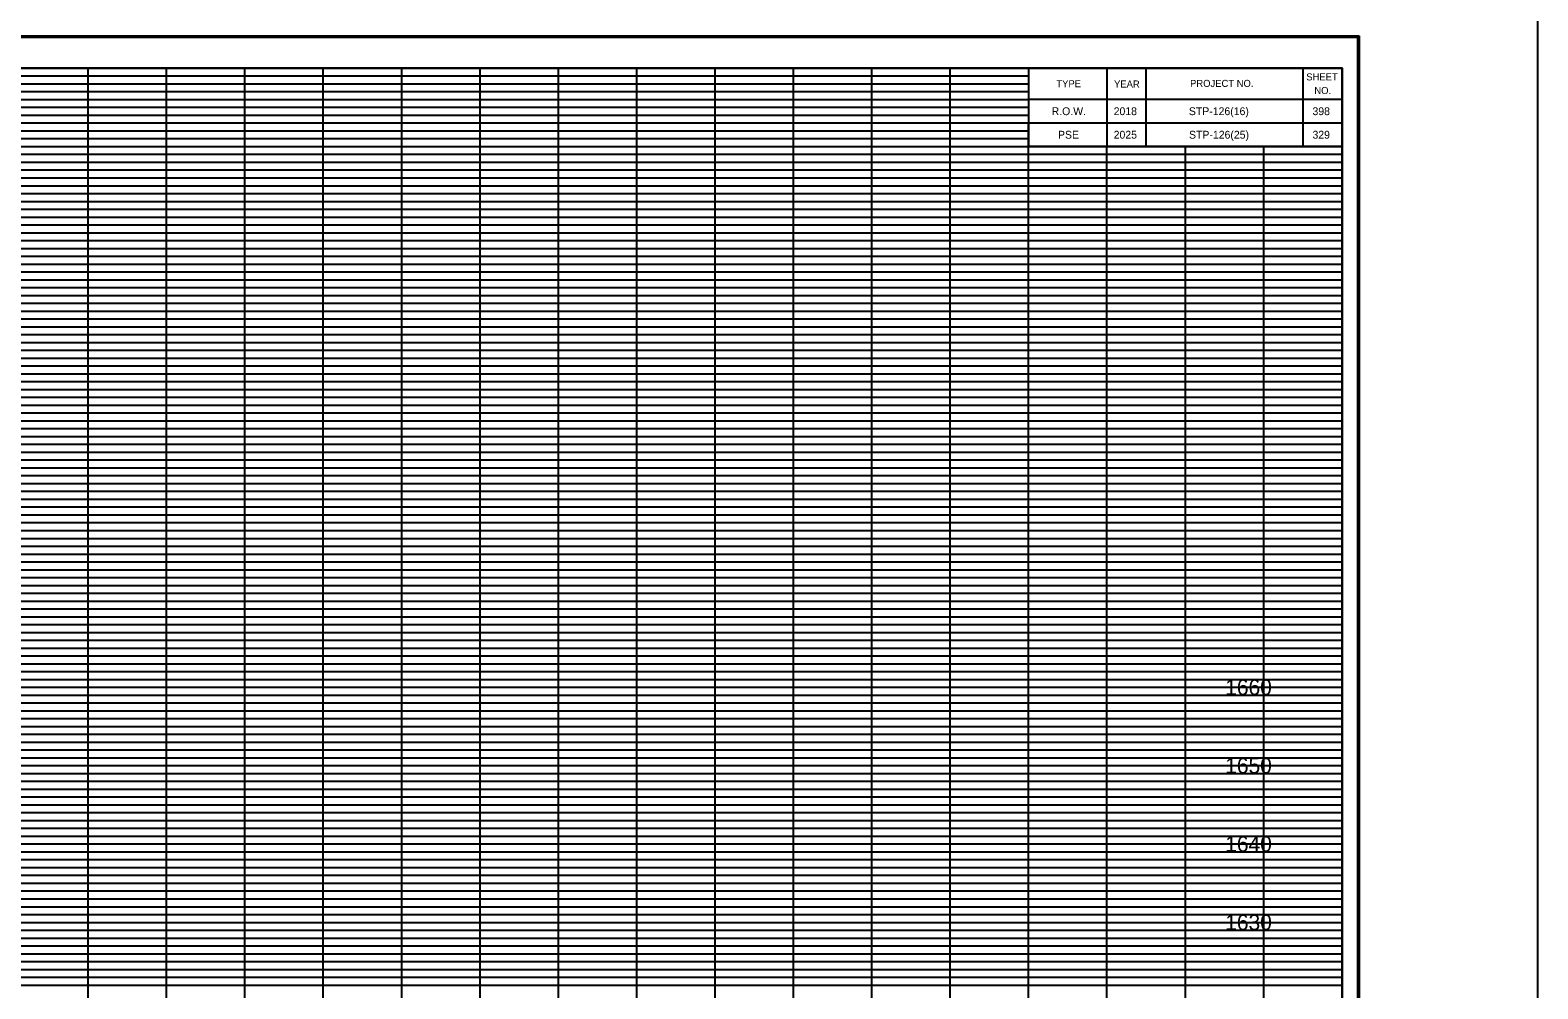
# Model space of a CAD drawing. Extents: x 955 to 1375, y 1248 to 3657.
# Drawn here: x 1152.6 to 1345, y 2982.5 to 3104.8 of the extents above; entities that cross this region are included whole.
import ezdxf

# ---------------------------------------------------------------- set-up
doc = ezdxf.new("R2010")
doc.units = 0
for name, color, linetype in [('DESIGN - SCRATCH - User 1', 7, 'Continuous'), ('DESIGN - SHEET - Corner Text', 7, 'Continuous'), ('DESIGN - SHEET - Light Grid', 7, 'Continuous'), ('DESIGN - SHEET - Linework', 7, 'Continuous'), ('DESIGN - SHEET - Plot Shape', 7, 'Continuous'), ('DESIGN - TYPICAL - Text', 7, 'Continuous'), ('DESIGN - UTILITIES - Cable (Overhead) with Text', 7, 'Continuous'), ('SURVEY - NON-TRANSPORTATION - Features Text', 7, 'Continuous')]:
    doc.layers.add(name, color=color, linetype=linetype)

# ---------------------------------------------------------------- blocks, each defined once
blk = doc.blocks.new('XSTSHT')
at = {"layer": 'DESIGN - SCRATCH - User 1'}
for p, q in [((28.5, 20.45), (28.5, 20.45)), ((29.24, 20.45), (29.24, 20.45)), ((30.49, 20.45), (30.49, 20.45)), ((31.74, 20.45), (31.74, 20.45)), ((28.5, 20.15), (28.5, 20.15)), ((29.24, 20.15), (29.24, 20.15)), ((30.49, 20.15), (30.49, 20.15)), ((31.74, 20.15), (31.74, 20.15))]:
    blk.add_line(p, q, dxfattribs=at)
at = {"layer": 'DESIGN - SHEET - Light Grid'}
for p, q in [((8, 20.9), (16, 20.9)), ((8, 20.8), (16, 20.8)), ((16, 20.9), (24, 20.9)), ((16, 20.8), (24, 20.8)), ((24, 20.9), (28, 20.9)), ((24, 20.8), (28, 20.8)), ((8, 20.7), (16, 20.7)), ((8, 20.6), (16, 20.6)), ((16, 20.7), (24, 20.7)), ((16, 20.6), (24, 20.6)), ((24, 20.7), (28, 20.7)), ((24, 20.6), (28, 20.6)), ((8, 20.5), (16, 20.5)), ((8, 20.4), (16, 20.4)), ((16, 20.5), (24, 20.5)), ((16, 20.4), (24, 20.4)), ((24, 20.5), (28, 20.5)), ((24, 20.4), (28, 20.4)), ((8, 20.3), (16, 20.3)), ((16, 20.3), (24, 20.3)), ((24, 20.3), (28, 20.3)), ((8, 20.2), (16, 20.2)), ((8, 20.1), (16, 20.1)), ((16, 20.2), (24, 20.2)), ((16, 20.1), (24, 20.1)), ((24, 20.2), (28, 20.2)), ((24, 20.1), (28, 20.1)), ((8, 19.9), (16, 19.9)), ((16, 19.9), (24, 19.9)), ((24, 19.9), (32, 19.9)), ((8, 19.8), (16, 19.8)), ((8, 19.7), (16, 19.7)), ((16, 19.8), (24, 19.8)), ((16, 19.7), (24, 19.7)), ((24, 19.8), (32, 19.8)), ((24, 19.7), (32, 19.7)), ((8, 19.6), (16, 19.6)), ((8, 19.5), (16, 19.5)), ((16, 19.6), (24, 19.6)), ((16, 19.5), (24, 19.5)), ((24, 19.6), (32, 19.6)), ((24, 19.5), (32, 19.5)), ((8, 19.4), (16, 19.4)), ((8, 19.3), (16, 19.3)), ((16, 19.4), (24, 19.4)), ((16, 19.3), (24, 19.3)), ((24, 19.4), (32, 19.4)), ((24, 19.3), (32, 19.3)), ((8, 19.2), (16, 19.2)), ((8, 19.1), (16, 19.1)), ((16, 19.2), (24, 19.2)), ((16, 19.1), (24, 19.1)), ((24, 19.2), (32, 19.2)), ((24, 19.1), (32, 19.1)), ((8, 18.9), (16, 18.9)), ((16, 18.9), (24, 18.9)), ((24, 18.9), (32, 18.9)), ((8, 18.8), (16, 18.8)), ((8, 18.7), (16, 18.7)), ((16, 18.8), (24, 18.8)), ((16, 18.7), (24, 18.7)), ((24, 18.8), (32, 18.8)), ((24, 18.7), (32, 18.7)), ((8, 18.6), (16, 18.6)), ((8, 18.5), (16, 18.5)), ((16, 18.6), (24, 18.6)), ((16, 18.5), (24, 18.5)), ((24, 18.6), (32, 18.6)), ((24, 18.5), (32, 18.5)), ((8, 18.4), (16, 18.4)), ((8, 18.3), (16, 18.3)), ((16, 18.4), (24, 18.4)), ((16, 18.3), (24, 18.3)), ((24, 18.4), (32, 18.4)), ((24, 18.3), (32, 18.3)), ((8, 18.2), (16, 18.2)), ((8, 18.1), (16, 18.1)), ((16, 18.2), (24, 18.2)), ((16, 18.1), (24, 18.1)), ((24, 18.2), (32, 18.2)), ((24, 18.1), (32, 18.1)), ((8, 17.9), (16, 17.9)), ((16, 17.9), (24, 17.9)), ((24, 17.9), (32, 17.9)), ((8, 17.8), (16, 17.8)), ((8, 17.7), (16, 17.7)), ((16, 17.8), (24, 17.8)), ((16, 17.7), (24, 17.7)), ((24, 17.8), (32, 17.8)), ((24, 17.7), (32, 17.7)), ((8, 17.6), (16, 17.6)), ((16, 17.6), (24, 17.6)), ((24, 17.6), (32, 17.6)), ((8, 17.5), (16, 17.5)), ((8, 17.4), (16, 17.4)), ((16, 17.5), (24, 17.5)), ((16, 17.4), (24, 17.4)), ((24, 17.5), (32, 17.5)), ((24, 17.4), (32, 17.4)), ((8, 17.3), (16, 17.3)), ((8, 17.2), (16, 17.2)), ((16, 17.3), (24, 17.3)), ((16, 17.2), (24, 17.2)), ((24, 17.3), (32, 17.3)), ((24, 17.2), (32, 17.2)), ((8, 17.1), (16, 17.1)), ((16, 17.1), (24, 17.1)), ((24, 17.1), (32, 17.1)), ((8, 16.9), (16, 16.9)), ((8, 16.8), (16, 16.8)), ((16, 16.9), (24, 16.9)), ((16, 16.8), (24, 16.8)), ((24, 16.9), (32, 16.9)), ((24, 16.8), (32, 16.8)), ((8, 16.7), (16, 16.7)), ((8, 16.6), (16, 16.6)), ((16, 16.7), (24, 16.7)), ((16, 16.6), (24, 16.6)), ((24, 16.7), (32, 16.7)), ((24, 16.6), (32, 16.6)), ((8, 16.5), (16, 16.5)), ((8, 16.4), (16, 16.4)), ((16, 16.5), (24, 16.5)), ((16, 16.4), (24, 16.4)), ((24, 16.5), (32, 16.5)), ((24, 16.4), (32, 16.4)), ((8, 16.3), (16, 16.3)), ((8, 16.2), (16, 16.2)), ((16, 16.3), (24, 16.3)), ((16, 16.2), (24, 16.2)), ((24, 16.3), (32, 16.3)), ((24, 16.2), (32, 16.2)), ((8, 16.1), (16, 16.1)), ((16, 16.1), (24, 16.1)), ((24, 16.1), (32, 16.1)), ((8, 15.9), (16, 15.9)), ((8, 15.8), (16, 15.8)), ((16, 15.9), (24, 15.9)), ((16, 15.8), (24, 15.8)), ((24, 15.9), (32, 15.9)), ((24, 15.8), (32, 15.8)), ((8, 15.7), (16, 15.7)), ((8, 15.6), (16, 15.6)), ((16, 15.7), (24, 15.7)), ((16, 15.6), (24, 15.6)), ((24, 15.7), (32, 15.7)), ((24, 15.6), (32, 15.6)), ((8, 15.5), (16, 15.5)), ((8, 15.4), (16, 15.4)), ((16, 15.5), (24, 15.5)), ((16, 15.4), (24, 15.4)), ((24, 15.5), (32, 15.5)), ((24, 15.4), (32, 15.4)), ((8, 15.3), (16, 15.3)), ((8, 15.2), (16, 15.2)), ((16, 15.3), (24, 15.3)), ((16, 15.2), (24, 15.2)), ((24, 15.3), (32, 15.3)), ((24, 15.2), (32, 15.2)), ((8, 15.1), (16, 15.1)), ((16, 15.1), (24, 15.1)), ((24, 15.1), (32, 15.1)), ((8, 14.9), (16, 14.9)), ((16, 14.9), (24, 14.9)), ((24, 14.9), (32, 14.9)), ((8, 14.8), (16, 14.8)), ((8, 14.7), (16, 14.7)), ((16, 14.8), (24, 14.8)), ((16, 14.7), (24, 14.7)), ((24, 14.8), (32, 14.8)), ((24, 14.7), (32, 14.7)), ((8, 14.6), (16, 14.6)), ((8, 14.5), (16, 14.5)), ((16, 14.6), (24, 14.6)), ((16, 14.5), (24, 14.5)), ((24, 14.6), (32, 14.6)), ((24, 14.5), (32, 14.5)), ((8, 14.4), (16, 14.4)), ((8, 14.3), (16, 14.3)), ((16, 14.4), (24, 14.4)), ((16, 14.3), (24, 14.3)), ((24, 14.4), (32, 14.4)), ((24, 14.3), (32, 14.3)), ((8, 14.2), (16, 14.2)), ((8, 14.1), (16, 14.1)), ((16, 14.2), (24, 14.2)), ((16, 14.1), (24, 14.1)), ((24, 14.2), (32, 14.2)), ((24, 14.1), (32, 14.1)), ((8, 13.9), (16, 13.9)), ((16, 13.9), (24, 13.9)), ((24, 13.9), (32, 13.9)), ((8, 13.8), (16, 13.8)), ((8, 13.7), (16, 13.7)), ((16, 13.8), (24, 13.8)), ((16, 13.7), (24, 13.7)), ((24, 13.8), (32, 13.8)), ((24, 13.7), (32, 13.7)), ((8, 13.6), (16, 13.6)), ((8, 13.5), (16, 13.5)), ((16, 13.6), (24, 13.6)), ((16, 13.5), (24, 13.5)), ((24, 13.6), (32, 13.6)), ((24, 13.5), (32, 13.5)), ((8, 13.4), (16, 13.4)), ((8, 13.3), (16, 13.3)), ((16, 13.4), (24, 13.4)), ((16, 13.3), (24, 13.3)), ((24, 13.4), (32, 13.4)), ((24, 13.3), (32, 13.3)), ((8, 13.2), (16, 13.2)), ((8, 13.1), (16, 13.1)), ((16, 13.2), (24, 13.2)), ((16, 13.1), (24, 13.1)), ((24, 13.2), (32, 13.2)), ((24, 13.1), (32, 13.1)), ((8, 12.9), (16, 12.9)), ((16, 12.9), (24, 12.9)), ((24, 12.9), (32, 12.9)), ((8, 12.8), (16, 12.8)), ((8, 12.7), (16, 12.7)), ((16, 12.8), (24, 12.8)), ((16, 12.7), (24, 12.7)), ((24, 12.8), (32, 12.8)), ((24, 12.7), (32, 12.7)), ((8, 12.6), (16, 12.6)), ((16, 12.6), (24, 12.6)), ((24, 12.6), (32, 12.6)), ((8, 12.5), (16, 12.5)), ((8, 12.4), (16, 12.4)), ((16, 12.5), (24, 12.5)), ((16, 12.4), (24, 12.4)), ((24, 12.5), (32, 12.5)), ((24, 12.4), (32, 12.4)), ((8, 12.3), (16, 12.3)), ((8, 12.2), (16, 12.2)), ((16, 12.3), (24, 12.3)), ((16, 12.2), (24, 12.2)), ((24, 12.3), (32, 12.3)), ((24, 12.2), (32, 12.2)), ((8, 12.1), (16, 12.1)), ((16, 12.1), (24, 12.1)), ((24, 12.1), (32, 12.1)), ((8, 11.9), (16, 11.9)), ((8, 11.8), (16, 11.8)), ((16, 11.9), (24, 11.9)), ((16, 11.8), (24, 11.8)), ((24, 11.9), (32, 11.9)), ((24, 11.8), (32, 11.8)), ((8, 11.7), (16, 11.7)), ((8, 11.6), (16, 11.6)), ((16, 11.7), (24, 11.7)), ((16, 11.6), (24, 11.6)), ((24, 11.7), (32, 11.7)), ((24, 11.6), (32, 11.6)), ((8, 11.5), (16, 11.5)), ((8, 11.4), (16, 11.4)), ((16, 11.5), (24, 11.5)), ((16, 11.4), (24, 11.4)), ((24, 11.5), (32, 11.5)), ((24, 11.4), (32, 11.4)), ((8, 11.3), (16, 11.3)), ((8, 11.2), (16, 11.2)), ((16, 11.3), (24, 11.3)), ((16, 11.2), (24, 11.2)), ((24, 11.3), (32, 11.3)), ((24, 11.2), (32, 11.2)), ((8, 11.1), (16, 11.1)), ((16, 11.1), (24, 11.1)), ((24, 11.1), (32, 11.1)), ((8, 10.9), (16, 10.9)), ((8, 10.8), (16, 10.8)), ((16, 10.9), (24, 10.9)), ((16, 10.8), (24, 10.8)), ((24, 10.9), (32, 10.9)), ((24, 10.8), (32, 10.8)), ((8, 10.7), (16, 10.7)), ((8, 10.6), (16, 10.6)), ((16, 10.7), (24, 10.7)), ((16, 10.6), (24, 10.6)), ((24, 10.7), (32, 10.7)), ((24, 10.6), (32, 10.6)), ((8, 10.5), (16, 10.5)), ((8, 10.4), (16, 10.4)), ((16, 10.5), (24, 10.5)), ((16, 10.4), (24, 10.4)), ((24, 10.5), (32, 10.5)), ((24, 10.4), (32, 10.4)), ((8, 10.3), (16, 10.3)), ((8, 10.2), (16, 10.2)), ((16, 10.3), (24, 10.3)), ((16, 10.2), (24, 10.2)), ((24, 10.3), (32, 10.3)), ((24, 10.2), (32, 10.2)), ((8, 10.1), (16, 10.1)), ((16, 10.1), (24, 10.1)), ((24, 10.1), (32, 10.1)), ((8, 9.9), (16, 9.9)), ((16, 9.9), (24, 9.9)), ((24, 9.9), (32, 9.9)), ((8, 9.8), (16, 9.8)), ((8, 9.7), (16, 9.7)), ((16, 9.8), (24, 9.8)), ((16, 9.7), (24, 9.7)), ((24, 9.8), (32, 9.8)), ((24, 9.7), (32, 9.7)), ((8, 9.6), (16, 9.6)), ((8, 9.5), (16, 9.5)), ((16, 9.6), (24, 9.6)), ((16, 9.5), (24, 9.5)), ((24, 9.6), (32, 9.6)), ((24, 9.5), (32, 9.5)), ((8, 9.4), (16, 9.4)), ((8, 9.3), (16, 9.3)), ((16, 9.4), (24, 9.4)), ((16, 9.3), (24, 9.3)), ((24, 9.4), (32, 9.4)), ((24, 9.3), (32, 9.3))]:
    blk.add_line(p, q, dxfattribs=at)
at = {"layer": 'DESIGN - SHEET - Linework'}
for p, q in [((-1.823, 21.414), (32.217, 21.414)), ((32.217, 21.414), (32.217, -0.414)), ((16, 0), (16, 21)), ((17, 0), (17, 21)), ((18, 0), (18, 21)), ((19, 0), (19, 21)), ((20, 0), (20, 21)), ((21, 0), (21, 21)), ((22, 0), (22, 21)), ((23, 0), (23, 21)), ((24, 0), (24, 21)), ((25, 0), (25, 21)), ((26, 0), (26, 21)), ((27, 0), (27, 21)), ((0, 20), (28, 20)), ((28, 0), (28, 20)), ((29, 0), (29, 20)), ((30, 0), (30, 20)), ((31, 0), (31, 20)), ((0, 19), (32, 19)), ((0, 18), (32, 18)), ((0, 17), (32, 17)), ((0, 16), (32, 16)), ((0, 15), (32, 15)), ((0, 14), (32, 14)), ((0, 13), (32, 13)), ((0, 12), (32, 12)), ((0, 11), (32, 11)), ((0, 10), (32, 10))]:
    blk.add_line(p, q, dxfattribs=at)
for points in [[(0, 21), (0, 0), (32, 0), (32, 21), (0, 21)], [(28, 21), (28, 20), (32, 20), (32, 21), (31.5, 21), (31.5, 20), (29.5, 20), (29.5, 21), (29, 21), (29, 20), (32, 20), (28, 20), (28, 20.3), (32, 20.3), (32, 20.6), (28, 20.6)]]:
    blk.add_lwpolyline(points, dxfattribs=at)
at = {"layer": 'DESIGN - SHEET - Plot Shape'}
for points in [[(-1.803, 21.394), (32.197, 21.394), (32.197, -0.394), (-1.803, -0.394)], [(-0.85, 21), (32, 21), (32, -0.25), (-0.85, -0.25)]]:
    blk.add_lwpolyline(points, close=True, dxfattribs=at)
at = {"layer": 'DESIGN - SHEET - Corner Text'}
for s, p in [('TYPE', (28.354, 20.756)), ('YEAR', (29.09, 20.752)), ('PROJECT NO.', (30.06, 20.76)), ('SHEET', (31.543, 20.843)), ('NO.', (31.646, 20.669))]:
    blk.add_text(s, height=0.09, dxfattribs=at).set_placement(p)

msp = doc.modelspace()

# ---------------------------------------------------------------- linework, layer by layer
at = {"layer": 'DESIGN - SHEET - Plot Shape'}
msp.add_lwpolyline([(991.5, 2887.5), (1320, 2887.5), (1320, 3100), (991.5, 3100)], close=True, dxfattribs=at)
at = {"layer": 'SURVEY - NON-TRANSPORTATION - Features Text'}
msp.add_lwpolyline([(955.41, 1505.76), (1344.98, 1505.76), (1344.98, 3398.01), (955.41, 3398.01)], close=True, dxfattribs=at)

# ---------------------------------------------------------------- block references
at = {"layer": 'DESIGN - UTILITIES - Cable (Overhead) with Text', "xscale": 10, "yscale": 10}
msp.add_blockref('XSTSHT', (1000, 2890), dxfattribs=at)

# ---------------------------------------------------------------- texts
at = {"layer": 'DESIGN - SHEET - Corner Text'}
for s, p in [('R.O.W.', (1282.94, 3094)), ('2018', (1290.85, 3094)), ('STP-126(16)', (1300.45, 3094)), ('398', (1316.22, 3094)), ('PSE', (1283.75, 3091)), ('2025', (1290.85, 3091)), ('STP-126(25)', (1300.47, 3091)), ('329', (1316.22, 3091))]:
    msp.add_text(s, height=1, dxfattribs=at).set_placement(p)
at = {"layer": 'DESIGN - TYPICAL - Text'}
for s, p in [('     1660     ', (1301.37, 3020)), ('     1650     ', (1301.37, 3010)), ('     1640     ', (1301.37, 3000)), ('     1630     ', (1301.37, 2990))]:
    msp.add_text(s, height=2, dxfattribs=at).set_placement(p)

doc.saveas('drawing.dxf')
